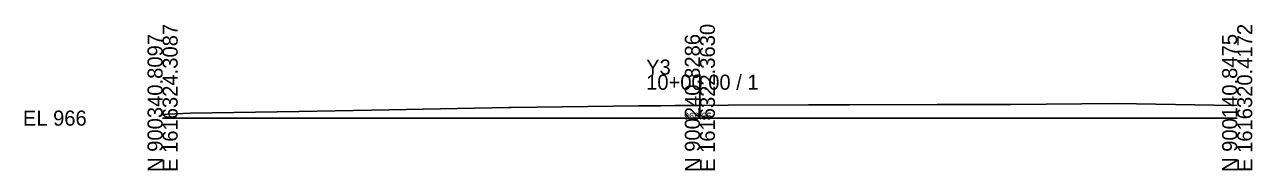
# Model space of a CAD drawing. Extents: x -26 to 203, y -10 to 2017.
# Drawn here: x -25.7 to 202.8, y -9.7 to 17.3 of the extents above; entities that cross this region are included whole.
import ezdxf

# ---------------------------------------------------------------- set-up
doc = ezdxf.new("R2010")
doc.units = 0
for name, color, linetype in [('Exist Cross Section Cell', 7, 'Continuous'), ('Exist XS Center Line Elevation Label', 7, 'Continuous'), ('Exist XS Ground Line', 7, 'Continuous')]:
    doc.layers.add(name, color=color, linetype=linetype)

msp = doc.modelspace()

# ---------------------------------------------------------------- linework, layer by layer
at = {"layer": 'Exist Cross Section Cell'}
for p, q in [((100, 0), (100, 8.06)), ((0, 0), (100, 0)), ((100, 0), (200, 0))]:
    msp.add_line(p, q, dxfattribs=at)
at = {"layer": 'Exist XS Ground Line'}
for p, q in [((64.89, 1.96), (88.61, 2.29)), ((88.61, 2.29), (92.72, 2.3)), ((92.72, 2.3), (95.34, 2.32)), ((95.34, 2.32), (100, 2.35)), ((100, 2.35), (105.27, 2.39)), ((105.27, 2.39), (120.19, 2.48)), ((120.19, 2.48), (125.01, 2.49)), ((125.01, 2.49), (125.55, 2.49)), ((125.55, 2.49), (127.82, 2.49)), ((127.82, 2.49), (144.18, 2.5)), ((144.18, 2.5), (147.12, 2.5)), ((147.12, 2.5), (157.85, 2.54)), ((157.85, 2.54), (177.65, 2.69)), ((177.65, 2.69), (195.7, 2.4)), ((195.7, 2.4), (200, 2.32)), ((0, 0.63), (0.84, 0.72)), ((0.84, 0.72), (5.18, 0.91)), ((5.18, 0.91), (25.34, 1.23)), ((25.34, 1.23), (38.91, 1.47)), ((38.91, 1.47), (45.34, 1.57)), ((45.34, 1.57), (64.42, 1.96)), ((64.42, 1.96), (64.89, 1.96))]:
    msp.add_line(p, q, dxfattribs=at)

# ---------------------------------------------------------------- texts
at = {"layer": 'Exist Cross Section Cell'}
for s, p in [('E 1616324.3087', (2.8, -10)), ('E 1616322.3630', (102.8, -10)), ('E 1616320.4172', (202.8, -10)), ('N 900340.8097', (0, -10)), ('N 900240.8286', (100, -10)), ('N 900140.8475', (200, -10))]:
    msp.add_text(s, height=2.8, rotation=90, dxfattribs=at).set_placement(p)
for s, p in [('Y3', (90, 8.06)), ('10+00.00 / 1', (90, 5.26)), ('EL 966', (-26, -1.4))]:
    msp.add_text(s, height=2.8, dxfattribs=at).set_placement(p)
at = {"layer": 'Exist XS Center Line Elevation Label'}
msp.add_text('968.35', height=1.25, dxfattribs=at).set_placement((97.07, -0.27))

doc.saveas('drawing.dxf')
